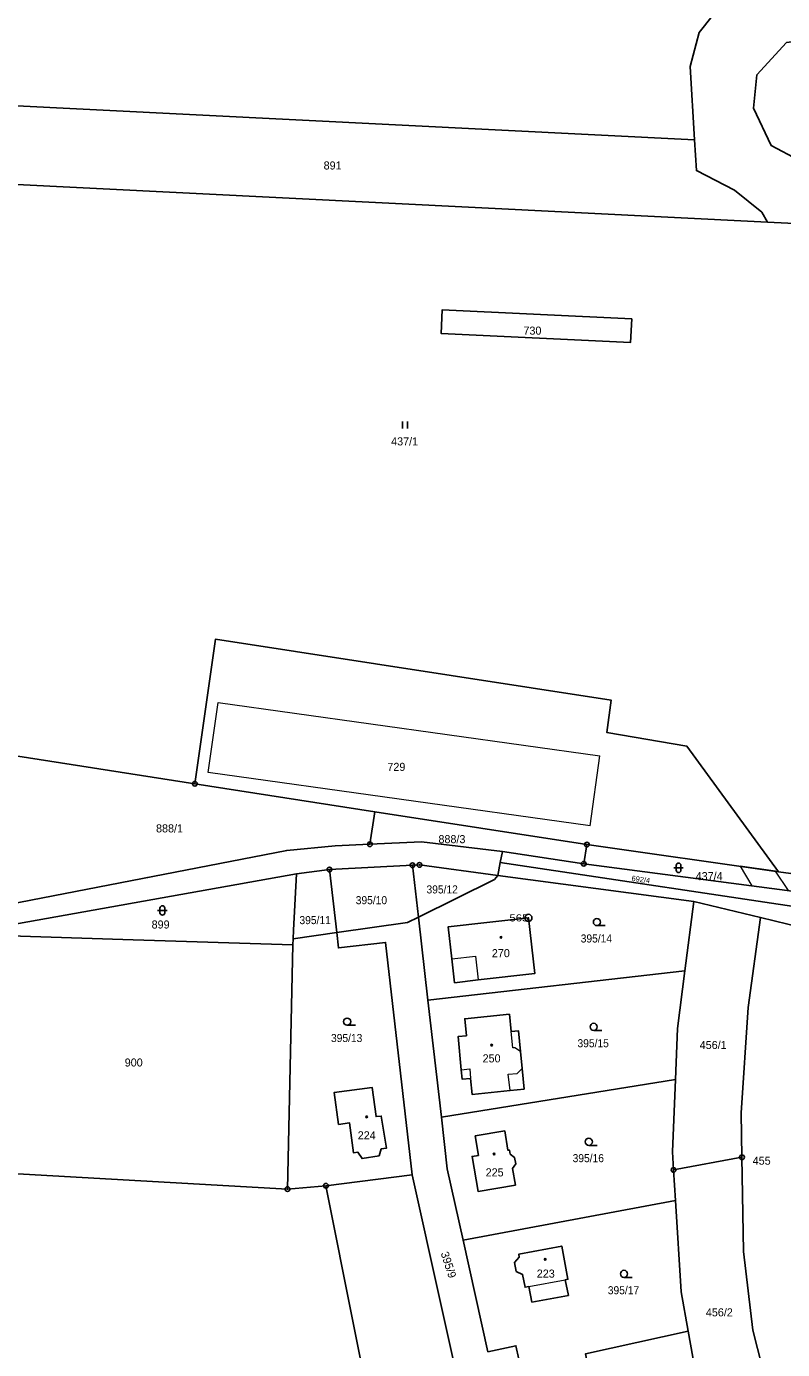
# Model space of a CAD drawing. Extents: x -758887 to -754328, y -1031688 to -1029144.
# Drawn here: x -756855.4 to -756696, y -1030326.2 to -1030047.3 of the extents above; entities that cross this region are included whole.
import ezdxf
from ezdxf.enums import TextEntityAlignment as Align

# ---------------------------------------------------------------- set-up
doc = ezdxf.new("R2010")
doc.units = 0
doc.header["$LTSCALE"] = 0.68
for name, color, linetype, lineweight in [('1', 7, 'Continuous', 25), ('13', 7, 'Continuous', 13), ('3', 7, 'Continuous', 25), ('4', 7, 'Continuous', 13), ('5', 7, 'Continuous', 25), ('8', 7, 'Continuous', 25)]:
    doc.layers.add(name, color=color, linetype=linetype, lineweight=lineweight)
doc.layers.add('2', color=7, linetype='Continuous')

msp = doc.modelspace()

# ---------------------------------------------------------------- linework, layer by layer
at = {"layer": '1'}
for p, q in [((-756714.54, -1030071.18), (-756867.25, -1030063.48)), ((-756699.14, -1030088.53), (-756867.57, -1030080.06)), ((-756783.01, -1030219.69), (-756781.95, -1030212.82)), ((-756737.24, -1030219.76), (-756737.93, -1030223.79)), ((-756737.24, -1030219.76), (-756696.82, -1030225.47)), ((-756755.06, -1030221.18), (-756755.52, -1030223.53)), ((-756737.93, -1030223.79), (-756755.06, -1030221.18)), ((-756791.54, -1030225.02), (-756798.46, -1030225.92)), ((-756774.03, -1030224.12), (-756791.54, -1030225.02)), ((-756791.54, -1030225.02), (-756790.01, -1030238.31)), ((-756772.78, -1030235.06), (-756774.03, -1030224.12)), ((-756755.52, -1030223.53), (-756756.06, -1030226.24)), ((-756714.7, -1030231.76), (-756756.06, -1030226.24)), ((-756687.12, -1030230.47), (-756737.93, -1030223.79)), ((-756716.59, -1030246.38), (-756714.7, -1030231.76)), ((-756714.7, -1030231.76), (-756700.62, -1030235.14)), ((-756700.62, -1030235.14), (-756691.98, -1030237.21)), ((-756799.21, -1030239.61), (-756790.01, -1030238.31)), ((-756770.77, -1030252.58), (-756716.59, -1030246.38)), ((-756718.59, -1030269.32), (-756767.94, -1030277.26)), ((-756704.7, -1030276.28), (-756704.55, -1030285.67)), ((-756718.97, -1030288.35), (-756704.55, -1030285.67)), ((-756704.55, -1030285.67), (-756704.22, -1030305.53)), ((-756792.27, -1030291.7), (-756774.11, -1030289.39)), ((-756758.16, -1030326.71), (-756763.37, -1030303.17))]:
    msp.add_line(p, q, dxfattribs=at)
for points in [[(-756714.54, -1030071.18), (-756715.46, -1030055.67), (-756713.59, -1030048.51), (-756708.08, -1030041.61), (-756699.67, -1030037.22), (-756689.23, -1030035.26), (-756679.35, -1030037.63), (-756661.63, -1030045.85), (-756652.95, -1030046.63), (-756646.8, -1030043.59), (-756643.15, -1030037.53), (-756645.12, -1030026.77), (-756653.71, -1030009.31), (-756668.42, -1029980.86), (-756678.83, -1029958.2), (-756692.28, -1029932.65), (-756697.98, -1029919.62)], [(-756632.94, -1030047.78), (-756636.08, -1030052.27), (-756644.58, -1030057.95), (-756653.82, -1030059.53), (-756672.95, -1030054.48), (-756685.27, -1030049.36), (-756695.13, -1030050.67), (-756701.44, -1030057.48), (-756702.14, -1030064.49), (-756698.41, -1030072.38), (-756692.57, -1030075.43), (-756668.51, -1030073.1), (-756625.31, -1030069.22), (-756616.02, -1030069.6)], [(-756699.14, -1030088.53), (-756700.35, -1030086.42), (-756706.13, -1030081.76), (-756714.16, -1030077.63), (-756714.54, -1030071.18)], [(-756867.57, -1030080.06), (-756861.83, -1030200.43), (-756819.91, -1030206.93)], [(-756685.29, -1030198.37), (-756679.09, -1030089.54), (-756699.14, -1030088.53)], [(-756819.91, -1030206.93), (-756815.55, -1030176.44), (-756732.12, -1030189.32), (-756733.07, -1030196.12), (-756716.15, -1030199.03), (-756696.82, -1030225.47)], [(-756696.82, -1030225.47), (-756686.91, -1030226.87), (-756685.29, -1030198.37)], [(-756819.91, -1030206.93), (-756781.95, -1030212.82), (-756737.24, -1030219.76)], [(-756783.01, -1030219.69), (-756790.33, -1030220.04), (-756800.55, -1030220.98), (-756859.23, -1030232.39), (-756860.34, -1030232.62), (-756870.29, -1030234.64)], [(-756755.06, -1030221.18), (-756772.13, -1030219.16), (-756783.01, -1030219.69)], [(-756798.46, -1030225.92), (-756869.75, -1030238.62), (-756867.75, -1030252.11)], [(-756798.46, -1030225.92), (-756799.11, -1030237.78), (-756799.21, -1030239.61)], [(-756756.06, -1030226.24), (-756772.57, -1030224.04), (-756774.03, -1030224.12)], [(-756772.78, -1030235.06), (-756756.77, -1030227.15), (-756756.06, -1030226.24)], [(-756685.47, -1030230.69), (-756685.18, -1030234.07), (-756755.52, -1030223.53)], [(-756772.78, -1030235.06), (-756775.06, -1030236.19), (-756790.01, -1030238.31)], [(-756767.94, -1030277.26), (-756770.77, -1030252.58), (-756772.78, -1030235.06)], [(-756700.62, -1030235.14), (-756703.22, -1030254.08), (-756704.7, -1030276.28)], [(-756869.75, -1030238.62), (-756832.89, -1030239.85), (-756799.28, -1030240.89)], [(-756799.21, -1030239.61), (-756799.28, -1030240.89), (-756800.38, -1030292.39), (-756792.27, -1030291.7)], [(-756790.01, -1030238.31), (-756789.64, -1030241.53), (-756779.71, -1030240.4), (-756774.11, -1030289.39), (-756762.04, -1030343.84), (-756752.66, -1030372.24), (-756740.95, -1030364.58)], [(-756718.59, -1030269.32), (-756718.16, -1030258.52), (-756716.59, -1030246.38)], [(-756867.75, -1030252.11), (-756862.3, -1030288.91), (-756800.38, -1030292.39)], [(-756718.59, -1030269.32), (-756719.2, -1030284.54), (-756718.97, -1030288.35), (-756718.57, -1030294.82)], [(-756767.94, -1030277.26), (-756766.7, -1030288.15), (-756763.37, -1030303.17), (-756718.57, -1030294.82)], [(-756792.27, -1030291.7), (-756780.45, -1030351.21), (-756774.23, -1030375.78), (-756770.36, -1030384.93), (-756769.91, -1030385.99)], [(-756715.91, -1030322.36), (-756717.4, -1030314.04), (-756718.57, -1030294.82)], [(-756704.22, -1030305.53), (-756702.27, -1030322.12), (-756698.31, -1030337.6)], [(-756715.91, -1030322.36), (-756737.58, -1030327.16), (-756735.61, -1030337.21)], [(-756711.05, -1030345.79), (-756713.81, -1030334.1), (-756715.91, -1030322.36)], [(-756757.54, -1030329.5), (-756751.61, -1030328.23), (-756752.21, -1030325.42), (-756758.16, -1030326.71)]]:
    msp.add_lwpolyline(points, dxfattribs=at)
for points in [[(-756727.81, -1030108.92), (-756728.06, -1030113.91), (-756768.01, -1030111.97), (-756767.77, -1030106.98)], [(-756765.19, -1030248.91), (-756760.19, -1030248.27), (-756748.21, -1030246.93), (-756749.6, -1030235.18), (-756766.48, -1030237.09), (-756765.71, -1030243.86)], [(-756753.55, -1030255.52), (-756763, -1030256.48), (-756762.66, -1030260.06), (-756764.4, -1030260.22), (-756763.74, -1030267.23), (-756763.56, -1030269.21), (-756761.82, -1030269.08), (-756761.47, -1030272.44), (-756753.44, -1030271.63), (-756750.5, -1030271.32), (-756750.9, -1030266.94), (-756751.23, -1030263.41), (-756751.64, -1030259.06), (-756753.21, -1030259.19)], [(-756781.06, -1030285.38), (-756780.62, -1030283.93), (-756779.52, -1030283.78), (-756780.63, -1030276.99), (-756781.72, -1030277.11), (-756782.56, -1030270.94), (-756790.53, -1030272.02), (-756789.62, -1030278.77), (-756787.3, -1030278.45), (-756786.45, -1030284.76), (-756785.52, -1030284.63), (-756784.64, -1030285.97)], [(-756752.93, -1030288.03), (-756752.27, -1030287.08), (-756752.52, -1030285.71), (-756753.45, -1030285.02), (-756753.6, -1030284.16), (-756753.89, -1030284.2), (-756754.58, -1030280.11), (-756760.78, -1030281.18), (-756760.11, -1030285.28), (-756761.45, -1030285.52), (-756760.2, -1030292.89), (-756752.32, -1030291.54)], [(-756748.84, -1030316.24), (-756741.16, -1030314.81), (-756741.8, -1030311.5), (-756741.25, -1030311.4), (-756742.55, -1030304.42), (-756751.63, -1030306.12), (-756751.51, -1030306.77), (-756752.53, -1030307.85), (-756752.16, -1030309.76), (-756750.81, -1030310.38), (-756750.29, -1030313.1), (-756749.47, -1030312.94)]]:
    msp.add_lwpolyline(points, close=True, dxfattribs=at)
at = {"layer": '13'}
msp.add_lwpolyline([(-756694.74, -1030229.47), (-756697.51, -1030225.37), (-756704.92, -1030224.33), (-756702.5, -1030228.45)], close=True, dxfattribs=at)
at = {"layer": '3'}
for p, q in [((-756776.101, -1030132.04), (-756776.101, -1030130.54)), ((-756775.1, -1030132.04), (-756775.1, -1030130.54)), ((-756718.931, -1030224.661), (-756716.929, -1030224.661)), ((-756718.431, -1030224.161), (-756718.431, -1030225.162)), ((-756717.429, -1030225.162), (-756717.429, -1030224.161)), ((-756827.771, -1030233.641), (-756825.769, -1030233.641)), ((-756827.271, -1030233.141), (-756827.271, -1030234.142)), ((-756826.269, -1030234.142), (-756826.269, -1030233.141)), ((-756735.143, -1030236.85), (-756733.393, -1030236.85)), ((-756787.803, -1030257.84), (-756786.053, -1030257.84)), ((-756735.823, -1030258.94), (-756734.073, -1030258.94)), ((-756736.853, -1030283.17), (-756735.103, -1030283.17)), ((-756729.433, -1030311.02), (-756727.683, -1030311.02))]:
    msp.add_line(p, q, dxfattribs=at)
for centre in [(-756735.1429, -1030236.0998), (-756787.8029, -1030257.0898), (-756735.8229, -1030258.1898), (-756736.8529, -1030282.4198), (-756729.4329, -1030310.2698)]:
    msp.add_circle(centre, 0.75, dxfattribs=at)
for centre, start, end in [((-756717.93, -1030224.1609), 0, 180), ((-756717.93, -1030225.1609), 180, 359.98789), ((-756826.77, -1030233.1409), 0, 180), ((-756826.77, -1030234.1409), 180, 359.98789)]:
    msp.add_arc(centre, 0.5, start, end, dxfattribs=at)
at = {"layer": '4'}
for p, q in [((-756736.56, -1030215.81), (-756734.5, -1030201.05)), ((-756765.71, -1030243.86), (-756760.73, -1030243.28)), ((-756760.73, -1030243.28), (-756760.19, -1030248.27)), ((-756763.74, -1030267.23), (-756761.97, -1030267.05)), ((-756761.97, -1030267.05), (-756761.82, -1030269.08)), ((-756749.47, -1030312.94), (-756741.8, -1030311.5))]:
    msp.add_line(p, q, dxfattribs=at)
for points in [[(-756736.56, -1030215.81), (-756817.13, -1030204.54), (-756815.01, -1030189.79), (-756734.5, -1030201.05)], [(-756751.23, -1030263.41), (-756752.46, -1030262.59), (-756752.86, -1030262.63), (-756753.21, -1030259.19)], [(-756753.44, -1030271.63), (-756753.83, -1030268.19), (-756751.98, -1030268.01), (-756750.9, -1030266.94)]]:
    msp.add_lwpolyline(points, dxfattribs=at)
at = {"layer": '5'}
for centre in [(-756755.3668, -1030239.3192), (-756757.3168, -1030262.0392), (-756783.6868, -1030277.1692), (-756756.8168, -1030285.0092), (-756746.0468, -1030307.2092)]:
    msp.add_circle(centre, 0.175, dxfattribs=at)
at = {"layer": '8'}
for centre, radius in [((-756819.91, -1030206.9299), 0.5), ((-756819.91, -1030206.9299), 0.0303), ((-756783.01, -1030219.6899), 0.5), ((-756783.01, -1030219.6899), 0.0303), ((-756737.24, -1030219.7599), 0.5), ((-756737.24, -1030219.7599), 0.0303), ((-756737.93, -1030223.7899), 0.5), ((-756791.54, -1030225.0199), 0.5), ((-756791.54, -1030225.0199), 0.0303), ((-756774.03, -1030224.1199), 0.5), ((-756774.03, -1030224.1199), 0.0303), ((-756772.57, -1030224.0399), 0.5), ((-756772.57, -1030224.0399), 0.0303), ((-756737.93, -1030223.7899), 0.0303), ((-756749.58, -1030235.2098), 0.75), ((-756749.58, -1030235.2098), 0.03), ((-756704.55, -1030285.6699), 0.5), ((-756704.55, -1030285.6699), 0.0303), ((-756718.97, -1030288.3499), 0.5), ((-756718.97, -1030288.3499), 0.0303), ((-756800.38, -1030292.3899), 0.5), ((-756800.38, -1030292.3899), 0.0303), ((-756792.27, -1030291.6999), 0.5), ((-756792.27, -1030291.6999), 0.0303)]:
    msp.add_circle(centre, radius, dxfattribs=at)

# ---------------------------------------------------------------- texts
at = {"layer": '2'}
for s, p in [('891', (-756790.869, -1030077.416)), ('730', (-756748.739, -1030112.24)), ('437/1', (-756775.69, -1030135.59)), ('729', (-756777.429, -1030204.22)), ('888/1', (-756825.26, -1030217.19)), ('888/3', (-756765.71, -1030219.46)), ('437/4', (-756711.48, -1030227.26)), ('899', (-756827.139, -1030237.456)), ('270', (-756755.399, -1030243.5)), ('900', (-756832.809, -1030266.546)), ('250', (-756757.349, -1030265.68)), ('224', (-756783.679, -1030281.9)), ('455', (-756700.399, -1030287.25)), ('225', (-756756.709, -1030289.72)), ('223', (-756745.929, -1030311.06))]:
    msp.add_text(s, height=1.7, dxfattribs=at).set_placement(p, align=Align.CENTER)
at = {"layer": '2', "width": 0.95}
for s, p in [('395/12', (-756767.769, -1030230.06)), ('395/10', (-756782.689, -1030232.33)), ('395/11', (-756794.559, -1030236.53)), ('395/14', (-756735.249, -1030240.4)), ('395/13', (-756787.909, -1030261.39)), ('395/15', (-756735.929, -1030262.49)), ('395/16', (-756736.959, -1030286.72)), ('395/17', (-756729.539, -1030314.57))]:
    msp.add_text(s, height=1.7, dxfattribs=at).set_placement(p, align=Align.CENTER)
at = {"layer": '2'}
for s, height, rotation, p in [('692/4', 1.14, 352, (-756725.9563, -1030227.6713)), ('395/9', 1.7, 288, (-756767.2211, -1030308.6178))]:
    msp.add_text(s, height=height, rotation=rotation, dxfattribs=at).set_placement(p, align=Align.CENTER)
for s, p in [('456/1', (-756713.47, -1030262.86)), ('456/2', (-756712.17, -1030319.23))]:
    msp.add_text(s, height=1.7, dxfattribs=at).set_placement(p)
at = {"layer": '8', "width": 1.2}
msp.add_text('565', height=1.5, dxfattribs=at).set_placement((-756749.58, -1030235.96), align=Align.RIGHT)

doc.saveas('drawing.dxf')
